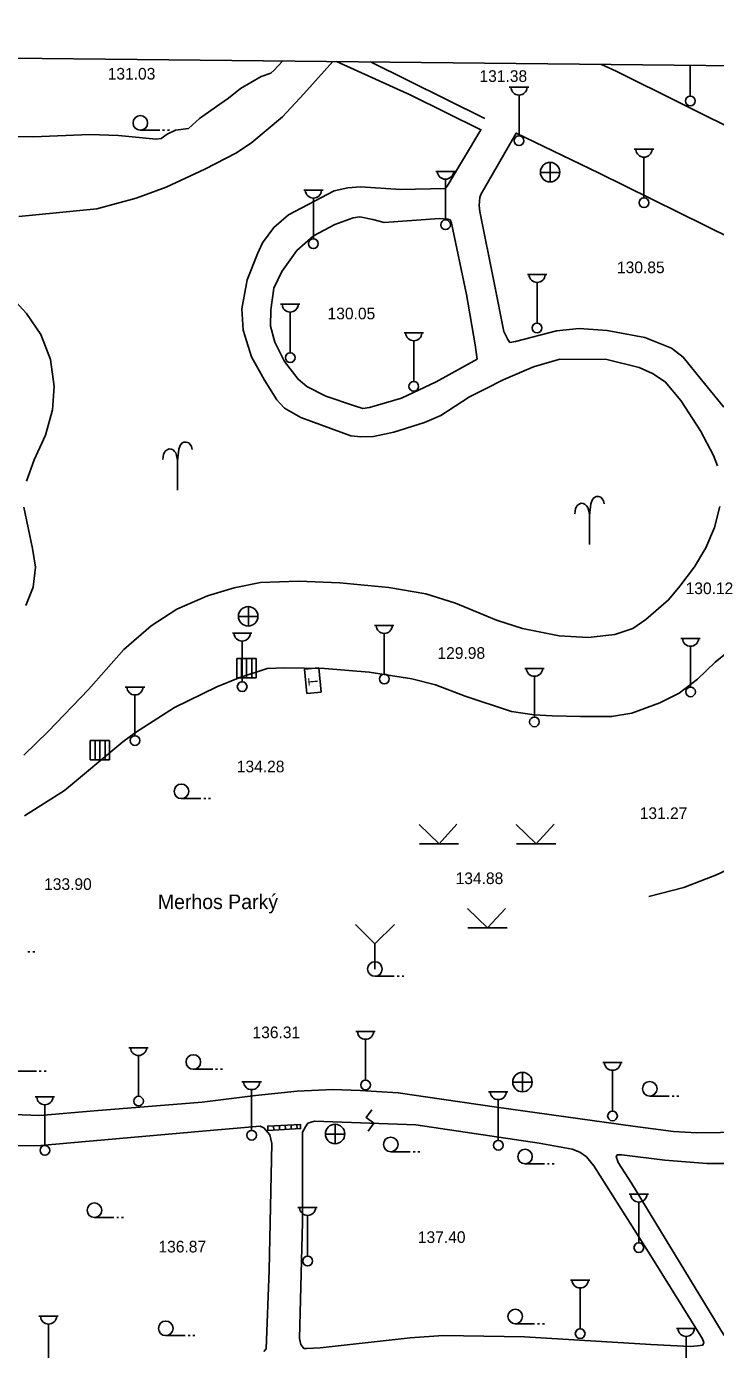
# Model space of a CAD drawing. Extents: x 419101 to 420177, y 4451541 to 4452254.
# Drawn here: x 419419.6 to 419490.6, y 4452109.6 to 4452245.8 of the extents above; entities that cross this region are included whole.
import ezdxf

# ---------------------------------------------------------------- set-up
doc = ezdxf.new("R2010")
doc.units = 0
doc.layers.add('0_ÖNERİ_LEJAND', color=7, linetype='Continuous')
doc.layers.add('3_HALİHAZIR', color=7, linetype='Continuous')

msp = doc.modelspace()

# ---------------------------------------------------------------- linework, layer by layer
at = {"layer": '0_ÖNERİ_LEJAND'}
msp.add_lwpolyline([(419108.72, 4452245.78), (420173.1, 4452234.54), (420165.77, 4451540.51), (419101.3, 4451551.75)], close=True, dxfattribs=at)
at = {"layer": '3_HALİHAZIR'}
for p, q in [((419487.98, 4452238.61), (419487.98, 4452241.77)), ((419469.34, 4452239.52), (419471.34, 4452239.52)), ((419470.34, 4452234.52), (419470.34, 4452238.71)), ((419431.33, 4452235.1), (419433.33, 4452235.1)), ((419433.63, 4452235.1), (419433.83, 4452235.1)), ((419434.13, 4452235.1), (419434.33, 4452235.1)), ((419482.21, 4452233.13), (419484.21, 4452233.13)), ((419483.21, 4452228.13), (419483.21, 4452232.32)), ((419461.77, 4452230.86), (419463.77, 4452230.86)), ((419473.56, 4452229.77), (419473.56, 4452231.77)), ((419462.77, 4452225.86), (419462.77, 4452230.06)), ((419472.54, 4452230.76), (419474.54, 4452230.76)), ((419448.16, 4452228.92), (419450.16, 4452228.92)), ((419449.16, 4452223.92), (419449.16, 4452228.11)), ((419471.2, 4452220.24), (419473.2, 4452220.24)), ((419472.2, 4452215.24), (419472.2, 4452219.43)), ((419445.77, 4452217.19), (419447.77, 4452217.19)), ((419446.77, 4452212.19), (419446.77, 4452216.38)), ((419458.5, 4452214.23), (419460.5, 4452214.23)), ((419459.5, 4452209.23), (419459.5, 4452213.42)), ((419442.46, 4452184.05), (419442.46, 4452186.05)), ((419441.44, 4452185.04), (419443.44, 4452185.04)), ((419440.82, 4452183.32), (419442.82, 4452183.32)), ((419455.46, 4452184.11), (419457.46, 4452184.11)), ((419456.46, 4452179.11), (419456.46, 4452183.3)), ((419441.82, 4452178.32), (419441.82, 4452182.51)), ((419487.01, 4452182.78), (419489.01, 4452182.78)), ((419488.01, 4452177.78), (419488.01, 4452181.97)), ((419443.26, 4452180.71), (419441.26, 4452180.71)), ((419441.26, 4452180.71), (419441.26, 4452178.71)), ((419443.26, 4452180.71), (419441.26, 4452180.71)), ((419441.26, 4452180.71), (419441.26, 4452178.71)), ((419441.77, 4452178.71), (419441.77, 4452180.71)), ((419442.26, 4452178.71), (419442.26, 4452180.71)), ((419442.81, 4452178.71), (419442.81, 4452180.71)), ((419443.26, 4452178.71), (419443.26, 4452180.71)), ((419443.26, 4452178.71), (419443.26, 4452180.71)), ((419470.93, 4452179.69), (419472.93, 4452179.69)), ((419429.78, 4452177.77), (419431.78, 4452177.77)), ((419441.26, 4452178.71), (419443.26, 4452178.71)), ((419441.26, 4452178.71), (419443.26, 4452178.71)), ((419471.93, 4452174.69), (419471.93, 4452178.89)), ((419430.78, 4452172.77), (419430.78, 4452176.97)), ((419428.17, 4452172.27), (419426.17, 4452172.27)), ((419426.17, 4452172.27), (419426.17, 4452170.27)), ((419428.17, 4452172.27), (419426.17, 4452172.27)), ((419426.17, 4452172.27), (419426.17, 4452170.27)), ((419426.68, 4452170.27), (419426.68, 4452172.27)), ((419427.17, 4452170.27), (419427.17, 4452172.27)), ((419427.72, 4452170.27), (419427.72, 4452172.27)), ((419428.17, 4452170.27), (419428.17, 4452172.27)), ((419428.17, 4452170.27), (419428.17, 4452172.27)), ((419426.17, 4452170.27), (419428.17, 4452170.27)), ((419426.17, 4452170.27), (419428.17, 4452170.27)), ((419435.57, 4452166.29), (419437.57, 4452166.29)), ((419437.87, 4452166.29), (419438.07, 4452166.29)), ((419438.37, 4452166.29), (419438.57, 4452166.29)), ((419462.1, 4452161.64), (419460.04, 4452163.63)), ((419462.1, 4452161.64), (419463.95, 4452163.65)), ((419472.1, 4452161.64), (419470.04, 4452163.63)), ((419472.1, 4452161.64), (419473.95, 4452163.65)), ((419460.08, 4452161.64), (419464.12, 4452161.64)), ((419470.08, 4452161.64), (419474.12, 4452161.64)), ((419467.1, 4452152.98), (419465.04, 4452154.97)), ((419467.1, 4452152.98), (419468.95, 4452154.99)), ((419455.49, 4452151.34), (419453.49, 4452153.34)), ((419455.49, 4452151.34), (419457.5, 4452153.34)), ((419465.08, 4452152.98), (419469.12, 4452152.98)), ((419419.75, 4452150.52), (419419.95, 4452150.52)), ((419420.25, 4452150.52), (419420.45, 4452150.52)), ((419455.49, 4452148.75), (419455.49, 4452151.34)), ((419455.49, 4452148), (419457.49, 4452148)), ((419457.79, 4452148), (419457.99, 4452148)), ((419458.29, 4452148), (419458.49, 4452148)), ((419453.53, 4452142.32), (419455.53, 4452142.32)), ((419454.53, 4452137.32), (419454.53, 4452141.51)), ((419430.15, 4452140.65), (419432.15, 4452140.65)), ((419431.15, 4452135.65), (419431.15, 4452139.85)), ((419418.62, 4452138.25), (419420.62, 4452138.25)), ((419420.92, 4452138.25), (419421.12, 4452138.25)), ((419421.42, 4452138.25), (419421.62, 4452138.25)), ((419436.79, 4452138.43), (419438.79, 4452138.43)), ((419439.09, 4452138.43), (419439.29, 4452138.43)), ((419439.59, 4452138.43), (419439.79, 4452138.43)), ((419478.97, 4452139.13), (419480.97, 4452139.13)), ((419479.97, 4452134.13), (419479.97, 4452138.32)), ((419441.8, 4452137.14), (419443.8, 4452137.14)), ((419469.69, 4452137.09), (419471.69, 4452137.09)), ((419470.71, 4452136.1), (419470.71, 4452138.1)), ((419420.5, 4452135.58), (419422.5, 4452135.58)), ((419442.8, 4452132.14), (419442.8, 4452136.33)), ((419467.2, 4452136.11), (419469.2, 4452136.11)), ((419483.81, 4452135.67), (419485.81, 4452135.67)), ((419486.11, 4452135.67), (419486.31, 4452135.67)), ((419486.61, 4452135.67), (419486.81, 4452135.67)), ((419421.5, 4452130.58), (419421.5, 4452134.77)), ((419468.2, 4452131.11), (419468.2, 4452135.31)), ((419447.46, 4452132.71), (419447.48, 4452132.3)), ((419451.41, 4452130.77), (419451.41, 4452132.77)), ((419444.46, 4452132.58), (419444.48, 4452132.13)), ((419445.06, 4452132.6), (419445.08, 4452132.17)), ((419445.66, 4452132.63), (419445.68, 4452132.2)), ((419446.26, 4452132.66), (419446.28, 4452132.23)), ((419446.86, 4452132.68), (419446.88, 4452132.27)), ((419450.39, 4452131.76), (419452.39, 4452131.76)), ((419457.13, 4452129.94), (419459.13, 4452129.94)), ((419459.43, 4452129.94), (419459.63, 4452129.94)), ((419459.93, 4452129.94), (419460.13, 4452129.94)), ((419470.96, 4452128.69), (419472.96, 4452128.69)), ((419473.26, 4452128.69), (419473.46, 4452128.69)), ((419473.76, 4452128.69), (419473.96, 4452128.69)), ((419481.68, 4452125.57), (419483.68, 4452125.57)), ((419482.68, 4452120.57), (419482.68, 4452124.76)), ((419447.56, 4452124.19), (419449.56, 4452124.19)), ((419448.56, 4452119.19), (419448.56, 4452123.38)), ((419426.6, 4452123.17), (419428.6, 4452123.17)), ((419428.9, 4452123.17), (419429.1, 4452123.17)), ((419429.4, 4452123.17), (419429.6, 4452123.17)), ((419475.64, 4452116.72), (419477.64, 4452116.72)), ((419476.64, 4452111.72), (419476.64, 4452115.91)), ((419420.88, 4452113.01), (419422.88, 4452113.01)), ((419421.88, 4452108.01), (419421.88, 4452112.21)), ((419433.95, 4452111.01), (419435.95, 4452111.01)), ((419436.25, 4452111.01), (419436.45, 4452111.01)), ((419436.75, 4452111.01), (419436.95, 4452111.01)), ((419469.95, 4452112.23), (419471.95, 4452112.23)), ((419472.25, 4452112.23), (419472.45, 4452112.23)), ((419472.75, 4452112.23), (419472.95, 4452112.23)), ((419486.56, 4452111.74), (419488.56, 4452111.74)), ((419487.56, 4452106.74), (419487.56, 4452110.94))]:
    msp.add_line(p, q, dxfattribs=at)
for points in [[(419445.97, 4452242.22), (419445.11, 4452241.29), (419444.79, 4452240.98), (419443.79, 4452240.63), (419441.64, 4452239.4), (419440.4, 4452238.38), (419439.53, 4452237.78), (419437.44, 4452236.3), (419436.28, 4452235.28), (419434.95, 4452235.09), (419434.11, 4452234.69), (419433.49, 4452234.24), (419432.95, 4452234.19), (419429.07, 4452234.57), (419426.14, 4452234.64), (419420.34, 4452234.42), (419412.1, 4452234.47)], [(419418.81, 4452226.21), (419426.85, 4452227.02), (419430.92, 4452228.11), (419433.99, 4452229.23), (419437.99, 4452231.09), (419441.25, 4452232.77), (419442.82, 4452233.85), (419445.97, 4452236.49), (419448.19, 4452238.83), (419451.16, 4452242.16)], [(419451.54, 4452242.16), (419459.19, 4452238.69), (419466.42, 4452235.15), (419462.95, 4452229.35), (419462.72, 4452229.09), (419458.16, 4452228.99), (419454.02, 4452229.27), (419452.71, 4452229.17), (419451.31, 4452228.86), (419446.6, 4452226.37), (419445.08, 4452225.09), (419443.9, 4452223.5), (419443.39, 4452222.37), (419442.35, 4452219.71), (419441.79, 4452216.7), (419441.92, 4452214.51), (419442.77, 4452211.76), (419444.12, 4452209.37), (419445.38, 4452207.34), (419445.71, 4452207.01), (419446.19, 4452206.48), (419447.86, 4452205.52), (419453.01, 4452203.63), (419454.03, 4452203.52), (419455.35, 4452203.57), (419457.43, 4452204), (419460.6, 4452205.01), (419462.3, 4452205.74), (419465.25, 4452207.64), (419466.89, 4452208.49), (419468.72, 4452209.4), (419471.83, 4452210.73), (419474.55, 4452211.54), (419479.39, 4452211.49), (419482.7, 4452210.68), (419484.08, 4452210.07), (419485.39, 4452209.2), (419487.01, 4452207.29), (419489.02, 4452204.15), (419490.38, 4452201.62), (419490.79, 4452200.55)], [(419455.04, 4452242.12), (419466.83, 4452236.3)], [(419511.4, 4452241.52), (419511.72, 4452239.07), (419511.71, 4452236.37), (419511.03, 4452233.56), (419510.28, 4452231.15), (419509.64, 4452229.98), (419509.18, 4452229.47), (419508.84, 4452229.35), (419503.77, 4452229.92), (419502.83, 4452230.22), (419499.39, 4452231.75), (419493.82, 4452234.48), (419480.33, 4452241.16), (419478.84, 4452241.87)], [(419495.02, 4452222.58), (419478.61, 4452230.67), (419470.06, 4452234.8), (419466.41, 4452228.47), (419466.29, 4452228.18), (419466.24, 4452227.35), (419466.31, 4452226.74), (419467.77, 4452219.39), (419468.78, 4452214.36), (419469.18, 4452213.56), (419469.4, 4452213.26), (419469.99, 4452213.35), (419474.21, 4452214.45), (419476.53, 4452214.69), (419479.41, 4452214.48), (419483.31, 4452213.77), (419486.03, 4452212.65), (419487.26, 4452211.75), (419489.15, 4452209.41), (419491.42, 4452206.59)], [(419419.59, 4452198.97), (419420.4, 4452201.17), (419421.56, 4452203.71), (419422.29, 4452206.3), (419422.45, 4452208.72), (419422.08, 4452211.48), (419421.08, 4452214.07), (419419.62, 4452216.22), (419417.83, 4452218.17)], [(419433.66, 4452201.19), (419433.67, 4452201.48), (419433.73, 4452201.75), (419433.81, 4452201.92), (419433.9, 4452202.05), (419434.09, 4452202.21), (419434.29, 4452202.3), (419434.5, 4452202.27), (419434.7, 4452202.18), (419434.86, 4452202.03), (419434.99, 4452201.87), (419435.07, 4452201.61), (419435.11, 4452201.38), (419435.16, 4452201.05), (419435.16, 4452198.05)], [(419436.66, 4452202.23), (419436.59, 4452202.53), (419436.48, 4452202.75), (419436.32, 4452202.91), (419436.07, 4452202.98), (419435.83, 4452202.98), (419435.6, 4452202.87), (419435.44, 4452202.63), (419435.31, 4452202.25), (419435.16, 4452201.05)], [(419479.1, 4452196.63), (419479.03, 4452196.93), (419478.92, 4452197.15), (419478.76, 4452197.31), (419478.51, 4452197.38), (419478.27, 4452197.38), (419478.04, 4452197.27), (419477.88, 4452197.03), (419477.75, 4452196.65), (419477.6, 4452195.45)], [(419491.01, 4452196.36), (419490.49, 4452194.2), (419489.58, 4452192.09), (419488.41, 4452190.14), (419486.91, 4452188.16), (419485.74, 4452186.75), (419483.41, 4452184.74), (419482.06, 4452183.79), (419480.22, 4452183.18), (419477.46, 4452182.86), (419474.46, 4452183.05), (419470.71, 4452183.79), (419468.03, 4452184.65), (419463.79, 4452186.4), (419460.73, 4452187.38), (419456.92, 4452188.03), (419451.89, 4452188.5), (419447.61, 4452188.67), (419443.72, 4452188.55), (419440.99, 4452188), (419438.24, 4452187.16), (419435.08, 4452185.79), (419432.46, 4452184.08), (419429.63, 4452181.63), (419426.01, 4452177.54), (419421.84, 4452173.21), (419419.34, 4452170.78)], [(419419.53, 4452186.17), (419420.29, 4452188.06), (419420.52, 4452190.1), (419420.24, 4452192.05), (419419.34, 4452196.28)], [(419476.1, 4452195.59), (419476.11, 4452195.88), (419476.17, 4452196.15), (419476.25, 4452196.32), (419476.34, 4452196.45), (419476.53, 4452196.61), (419476.73, 4452196.7), (419476.94, 4452196.67), (419477.14, 4452196.58), (419477.3, 4452196.43), (419477.43, 4452196.27), (419477.51, 4452196.01), (419477.55, 4452195.78), (419477.6, 4452195.45), (419477.6, 4452192.45)], [(419419.39, 4452164.52), (419423.51, 4452167.13), (419429.52, 4452172.14), (419430.83, 4452173.09), (419434.86, 4452175.66), (419439.2, 4452177.81), (419441.57, 4452178.77), (419444.38, 4452179.67), (419446.18, 4452179.77), (419450.3, 4452179.7), (419454.92, 4452179.31), (419459.29, 4452178.63), (419461.72, 4452178.01), (419464.79, 4452176.83), (419469.56, 4452175.26), (419471.89, 4452174.9), (419473.74, 4452174.81), (419476.68, 4452174.76), (419479.87, 4452174.73), (419481.95, 4452175.09), (419484.86, 4452176.14), (419486.85, 4452177.16), (419488.74, 4452178.58), (419490.54, 4452180.33), (419493.01, 4452182.34)], [(419449.73, 4452179.75), (419448.24, 4452179.61)], [(419448.47, 4452177.12), (419448.24, 4452179.61)], [(419449.96, 4452177.26), (419449.73, 4452179.75)], [(419448.47, 4452177.12), (419449.96, 4452177.26)], [(419483.7, 4452156.2), (419487.33, 4452157.13), (419490.67, 4452158.44), (419494.05, 4452160.02), (419497.22, 4452161.78), (419500.15, 4452163.66), (419504.19, 4452167.03)], [(419503.32, 4452132.09), (419488.66, 4452131.89), (419486.24, 4452132.04), (419482.05, 4452132.58), (419468.02, 4452134.54), (419460.72, 4452135.59), (419457.88, 4452135.99), (419453.97, 4452136.25), (419451.15, 4452136.35), (419447.48, 4452136.17), (419443.2, 4452135.73), (419437.69, 4452135.05), (419426.57, 4452134.15), (419420.97, 4452133.68), (419416.37, 4452133.83)], [(419454.81, 4452132.07), (419455.4, 4452132.88), (419454.59, 4452133.47), (419455.18, 4452134.27)], [(419444.06, 4452109.36), (419444.31, 4452109.65), (419444.61, 4452117.75), (419444.89, 4452130.79), (419444.67, 4452131.69), (419444.04, 4452132.39), (419443.66, 4452132.56), (419438.12, 4452132.1), (419423.76, 4452130.81), (419421.08, 4452130.58), (419416.54, 4452130.55)], [(419496.37, 4452128.74), (419489.69, 4452128.73), (419485.35, 4452129.07), (419480.93, 4452129.62), (419480.45, 4452129.61), (419480.36, 4452129.44), (419480.54, 4452128.82), (419481.92, 4452126.69), (419491.47, 4452111.02)]]:
    msp.add_lwpolyline(points, dxfattribs=at)
for points in [[(419454.93, 4452206.55), (419458.22, 4452207.5), (419461.8, 4452209.21), (419466.03, 4452211.53), (419465.83, 4452213), (419464.92, 4452218.17), (419463.39, 4452225.54), (419463.24, 4452225.86), (419463.02, 4452225.94), (419462.14, 4452226.01), (419456.44, 4452225.59), (419455.27, 4452225.92), (419453.95, 4452226.18), (419453.25, 4452226.09), (419451.36, 4452225.39), (419449.17, 4452224.24), (419447.44, 4452222.7), (419445.91, 4452220.57), (419445.1, 4452218.83), (419444.76, 4452216.61), (419444.74, 4452214.93), (419445.19, 4452213.29), (419446.17, 4452211.28), (419447.58, 4452209.47), (419448.5, 4452208.72), (419450.43, 4452207.71), (419453.29, 4452206.76), (419454.25, 4452206.46)], [(419444.48, 4452132.13), (419444.46, 4452132.58), (419447.84, 4452132.73), (419447.84, 4452132.32)], [(419449.84, 4452109.76), (419459.12, 4452110.79), (419462.53, 4452111.01), (419470.9, 4452110.88), (419483.92, 4452110.08), (419487.97, 4452109.89), (419488.73, 4452109.95), (419489.27, 4452110.02), (419489.37, 4452110.29), (419489.24, 4452110.67), (419483.91, 4452119.23), (419478.06, 4452128.49), (419477.28, 4452129.43), (419476.6, 4452129.9), (419475.82, 4452130.2), (419472.41, 4452130.82), (419459.7, 4452132.71), (419449.27, 4452133.09), (419448.59, 4452132.88), (419448.33, 4452132.51), (419448.05, 4452131.96), (419448.05, 4452122.68), (419447.74, 4452110.7), (419447.85, 4452110.09), (419448.16, 4452109.7), (419448.49, 4452109.67)]]:
    msp.add_lwpolyline(points, close=True, dxfattribs=at)
for centre, radius in [((419487.98, 4452238.11), 0.5), ((419431.33, 4452235.85), 0.75), ((419470.34, 4452234.02), 0.5), ((419473.54, 4452230.78), 1), ((419483.21, 4452227.63), 0.5), ((419462.77, 4452225.36), 0.5), ((419449.16, 4452223.42), 0.5), ((419472.2, 4452214.74), 0.5), ((419446.77, 4452211.69), 0.5), ((419459.5, 4452208.73), 0.5), ((419442.44, 4452185.06), 1), ((419456.46, 4452178.61), 0.5), ((419441.82, 4452177.82), 0.5), ((419488.01, 4452177.28), 0.5), ((419471.93, 4452174.19), 0.5), ((419430.78, 4452172.27), 0.5), ((419435.57, 4452167.04), 0.75), ((419455.49, 4452148.75), 0.75), ((419436.79, 4452139.18), 0.75), ((419454.53, 4452136.82), 0.5), ((419470.69, 4452137.11), 1), ((419483.81, 4452136.42), 0.75), ((419431.15, 4452135.15), 0.5), ((419479.97, 4452133.63), 0.5), ((419451.39, 4452131.77), 1), ((419442.8, 4452131.64), 0.5), ((419457.13, 4452130.69), 0.75), ((419421.5, 4452130.08), 0.5), ((419468.2, 4452130.61), 0.5), ((419470.96, 4452129.44), 0.75), ((419426.6, 4452123.92), 0.75), ((419482.68, 4452120.07), 0.5), ((419448.56, 4452118.69), 0.5), ((419469.95, 4452112.98), 0.75), ((419433.95, 4452111.76), 0.75), ((419476.64, 4452111.22), 0.5)]:
    msp.add_circle(centre, radius, dxfattribs=at)
for centre in [(419470.34, 4452239.55), (419483.21, 4452233.16), (419462.77, 4452230.89), (419449.16, 4452228.95), (419472.2, 4452220.27), (419446.77, 4452217.22), (419459.5, 4452214.26), (419441.82, 4452183.35), (419456.46, 4452184.14), (419488.01, 4452182.81), (419471.93, 4452179.72), (419430.78, 4452177.8), (419454.53, 4452142.35), (419431.15, 4452140.68), (419479.97, 4452139.16), (419442.8, 4452137.17), (419421.5, 4452135.61), (419468.2, 4452136.14), (419482.68, 4452125.6), (419448.56, 4452124.22), (419476.64, 4452116.75), (419421.88, 4452113.04), (419487.56, 4452111.77)]:
    msp.add_arc(centre, 0.837, 183.298, 356.9072, dxfattribs=at)

# ---------------------------------------------------------------- texts
for s, height, rotation, p in [('131.03 ', 1.2, 359.998, (419427.97, 4452240.31)), ('131.38 ', 1.2, 359.998, (419466.27, 4452240.07)), ('130.85 ', 1.2, 359.998, (419480.43, 4452220.38)), ('130.05 ', 1.2, 359.998, (419450.62, 4452215.63)), ('130.12 ', 1.2, 359.998, (419487.5, 4452187.34)), ('129.98 ', 1.2, 359.998, (419461.94, 4452180.68)), ('T', 1, 95.3565, (419449.68, 4452177.98)), ('134.28 ', 1.2, 359.998, (419441.27, 4452169)), ('131.27 ', 1.2, 359.998, (419482.77, 4452164.19)), ('134.88 ', 1.2, 359.998, (419463.81, 4452157.49)), ('133.90 ', 1.2, 359.998, (419421.42, 4452156.89)), ('136.31 ', 1.2, 359.998, (419442.89, 4452141.63)), ('136.87 ', 1.2, 359.998, (419433.2, 4452119.57)), ('137.40 ', 1.2, 359.998, (419459.92, 4452120.55))]:
    msp.add_text(s, height=height, rotation=rotation, dxfattribs=at).set_placement(p)
msp.add_text('Merhos Parký', height=1.5, dxfattribs=at).set_placement((419433.14, 4452154.92))

doc.saveas('drawing.dxf')
